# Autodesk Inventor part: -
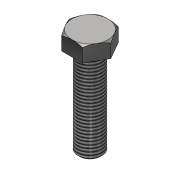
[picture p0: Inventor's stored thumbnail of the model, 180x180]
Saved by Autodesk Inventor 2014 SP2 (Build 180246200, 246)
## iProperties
Created: 2014-08
Part Number: -
Material: Stainless Steel
Document SubType Name: Modeling
Designer: dans
Mass: 463.662 g
Surface Area: 107.649 cm^2
Volume: 57.3839 cm^3
Density: 8.08 g/cm^3
Appearance: Stainless - Polished
Description: HEX BOLT-ISO 4017-A4-70 (316)-M24 x 90
Author: dans
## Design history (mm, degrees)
sketch "Sketch1"
  geometry: L1 (10.392, 18)-(20.785, 0); L2 (20.785, 0)-(10.392, -18); L3 (10.392, -18)-(-10.392, -18); L4 (-10.392, -18)-(-20.785, 0); L5 (-20.785, 0)-(-10.392, 18); L6 (-10.392, 18)-(10.392, 18); 2 further points
  constraints: 12 end point, 1 coincident, 1 horizontal, 13 other
  dimensions: "HEX_FLATS" = 36 distance between parallel lines of L3 L6
extrude "Extrusion1" new body sketch "Sketch1" taper "d2" = 0 deg; distance "HEX_THICK" = 15
sketch "Sketch2"
  geometry: L1 (10.392, 15)-(20.785, 15) reference; L2 (18, 15)-(30.7, 7.668); L3 (30.7, 7.668)-(30.7, 20.368); L4 (30.7, 20.368)-(18, 20.368); L5 (18, 20.368)-(18, 15); L6 (0, 29.021)-(0, -31.551) reference; L7 (0, 0)-(0, -22.898)
  constraints: 10 end point, 2 point on line, 2 vertical, 1 horizontal
  dimensions: "d3" = 30 deg angle of L2 L1; "HD_CHAMFER" = 18 distance between parallel lines of L5 L6; "d5" = 12.7 distance of L3.end L4.end; "d6" = 12.7 distance of L2.end L3.end
revolve "Revolution1" sketch "Sketch2" stored, may be unused: angle "d7" = 90 deg
sketch "Sketch3"
  geometry: C1 r 12 at (0, 0); 1 further point
  constraints: 1 centre point, 1 coincident
  dimensions: "BOLT_SIZE" = 24 diameter of C1
extrude "Extrusion2" join sketch "Sketch3" taper "d10" = 0 deg; distance "BOLT_LENGTH" = 90
chamfer "Chamfer1" distance "SHANK_CHAMFER" = 1.8; stored, may be unused: second distance "d12" = 3.175, angle "d13" = 45 deg
feature "Thread_M3" dims "d36" = 10, "d37" = 0
feature "Thread_M4" dims "d38" = 10, "d39" = 0
feature "Thread_M5" dims "d40" = 10, "d41" = 0
feature "Thread_M6" dims "d42" = 10, "d43" = 0
feature "Thread_M8" dims "d44" = 10, "d45" = 0
feature "Thread_M10" dims "d46" = 10, "d47" = 0
feature "Thread_M12" dims "d48" = 10, "d49" = 0
feature "Thread_M16" dims "d34" = 60, "d35" = 0
feature "Thread_M20" dims "d32" = 60, "d33" = 0
feature "Thread_M24" dims "d50" = 10, "d51" = 0
feature "Thread_M30" dims "d52" = 10, "d53" = 0
body "Solid1"
other parameters: "d19" = 0
